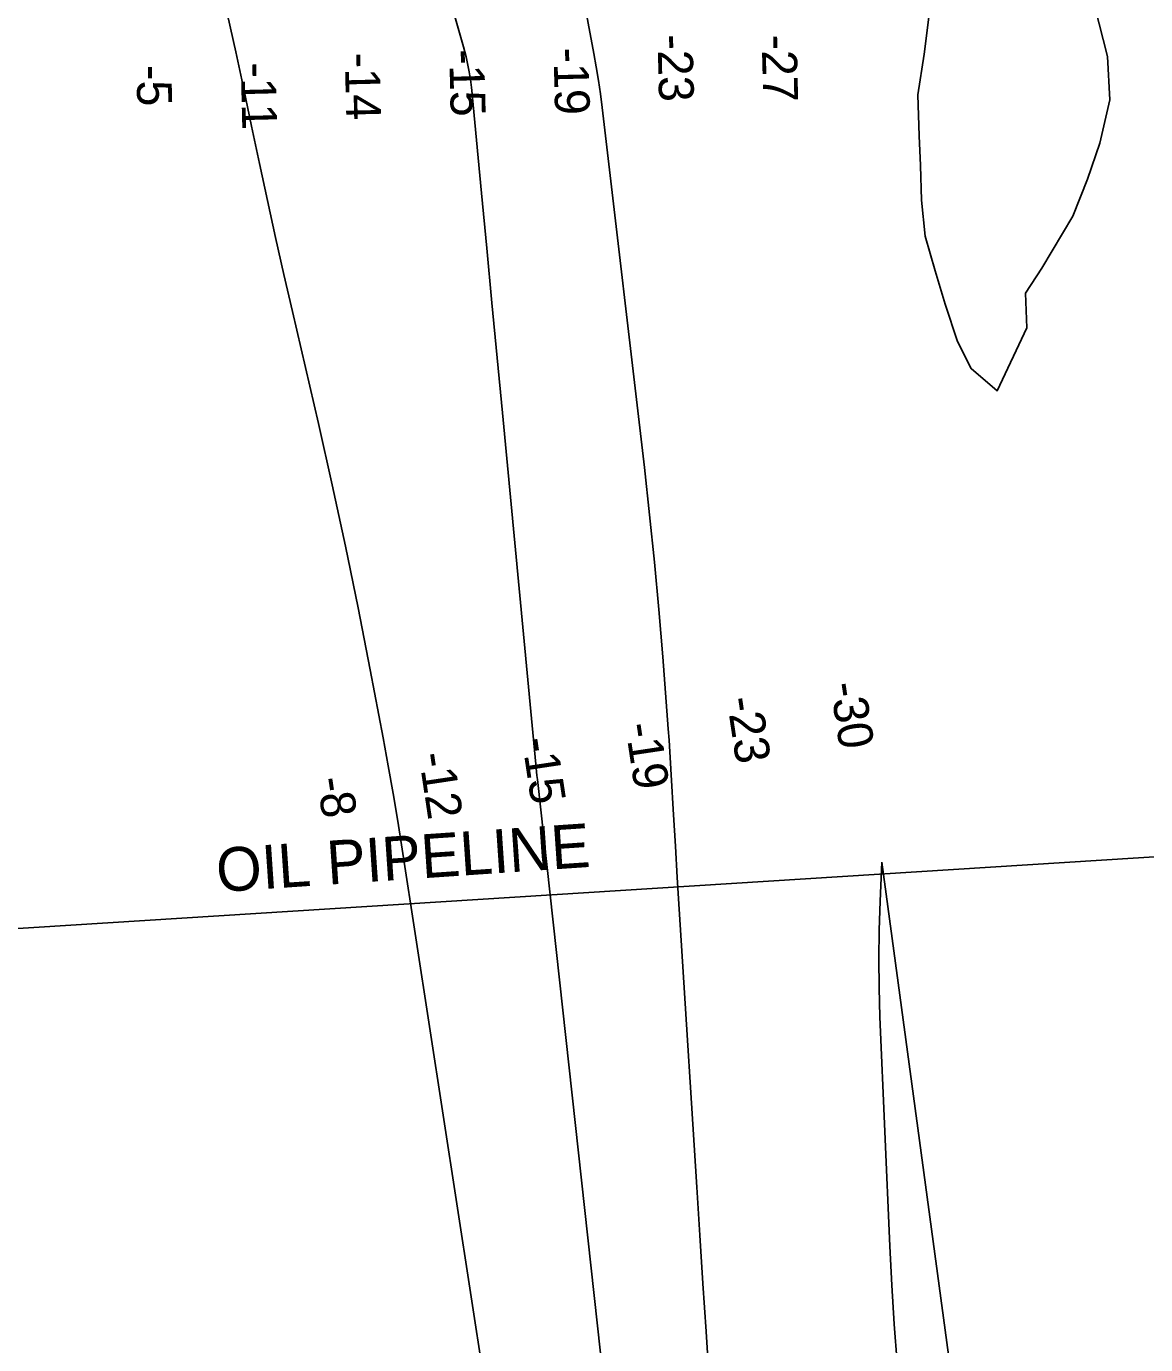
# Model space of a CAD drawing. Extents: x 3937982 to 3958556, y 219448 to 241894.
# Drawn here: x 3948252 to 3949325, y 230784 to 232047 of the extents above; entities that cross this region are included whole.
import ezdxf

# ---------------------------------------------------------------- set-up
doc = ezdxf.new("R2010")
doc.units = 0
for name, color, linetype in [('V-RIVR-EDGE', 7, 'Continuous'), ('V-RIVR-RANG', 7, 'Continuous'), ('V-TOPO-DPTH', 7, 'Continuous'), ('V-TOPO-MINR', 7, 'Continuous'), ('V-UTIL-IDEN', 7, 'Continuous'), ('V-UTIL-LINE', 7, 'Continuous')]:
    doc.layers.add(name, color=color, linetype=linetype)

msp = doc.modelspace()

# ---------------------------------------------------------------- linework, layer by layer
at = {"layer": 'V-RIVR-EDGE'}
msp.add_lwpolyline([(3949117.382, 232058.689), (3949112.633, 232020.698), (3949106.697, 231981.52), (3949107.884, 231942.342), (3949109.071, 231913.849), (3949110.258, 231880.607), (3949113.82, 231846.178), (3949123.318, 231812.936), (3949132.815, 231780.882), (3949144.687, 231745.265), (3949157.747, 231719.146), (3949182.678, 231697.777), (3949211.171, 231758.324), (3949209.984, 231791.566), (3949225.418, 231815.311), (3949255.098, 231865.174), (3949269.345, 231900.79), (3949281.217, 231935.219), (3949290.715, 231976.772), (3949288.34, 232018.324), (3949276.468, 232065.813)], dxfattribs=at)
at = {"layer": 'V-TOPO-DPTH'}
msp.add_line((3949335.18, 229299.97), (3949072.233, 231246.187), dxfattribs=at)
for points in [[(3948785.035, 232079.587), (3948796.105, 232021.135), (3948798.397, 232008.293), (3948800.507, 231995.422), (3948802.345, 231982.511), (3948804.001, 231969.571), (3948844.502, 231624.247), (3948849.537, 231578.945), (3948854.206, 231533.607), (3948858.326, 231488.216), (3948862.079, 231442.789), (3948867.355, 231373.85), (3948868.163, 231362.864), (3948868.927, 231351.876), (3948869.627, 231340.883), (3948870.284, 231329.887), (3948872.46, 231291.549), (3948874.202, 231261.383), (3948875.983, 231231.22), (3948877.823, 231201.061), (3948879.702, 231170.904), (3948894.659, 230934.576), (3948897.611, 230888.384), (3948900.601, 230842.195), (3948903.648, 230796.009), (3948906.732, 230749.826)], [(3948691.036, 230748.645), (3948612.317, 231258.504), (3948608.057, 231285.199), (3948603.617, 231311.864), (3948598.907, 231338.482), (3948594.018, 231365.07), (3948581.645, 231430.497), (3948570.072, 231489.699), (3948558.016, 231548.799), (3948545.235, 231607.746), (3948531.972, 231666.592), (3948507.119, 231773.786), (3948498.997, 231809.264), (3948491.005, 231844.771), (3948483.21, 231880.322), (3948475.545, 231915.902), (3948467.957, 231951.499), (3948460.341, 231987.089), (3948452.681, 232022.671), (3948444.992, 232058.246)], [(3948868.927, 231351.876), (3948869.627, 231340.883), (3948870.284, 231329.887), (3948872.46, 231291.549), (3948874.202, 231261.383), (3948875.983, 231231.22), (3948877.823, 231201.061), (3948879.702, 231170.904), (3948894.659, 230934.576), (3948897.611, 230888.384), (3948900.601, 230842.195), (3948903.648, 230796.009), (3948906.732, 230749.826)], [(3949086.893, 230765.99), (3949084.037, 230803.261), (3949081.756, 230840.571), (3949079.857, 230877.907), (3949070.364, 231097.917), (3949069.54, 231125.567), (3949069.208, 231153.217), (3949069.613, 231180.865), (3949070.509, 231208.513), (3949072.233, 231246.187)], [(3949072.233, 231246.187), (3949070.509, 231208.513), (3949069.613, 231180.865), (3949069.208, 231153.217), (3949069.54, 231125.567), (3949070.364, 231097.917), (3949079.857, 230877.907), (3949081.756, 230840.571), (3949084.037, 230803.261), (3949086.893, 230765.99)]]:
    msp.add_lwpolyline(points, dxfattribs=at)
at = {"layer": 'V-TOPO-MINR'}
for points in [[(3948484.624, 232682.01), (3948671.112, 232027.592), (3948672.419, 232022.851), (3948673.596, 232018.076), (3948674.683, 232013.282), (3948675.635, 232008.46), (3948676.498, 232003.619), (3948677.77, 231995.854), (3948678.03, 231994.162), (3948678.469, 231990.767), (3948678.649, 231989.065), (3948688.34, 231887.286), (3948693.347, 231834.692), (3948698.354, 231782.098), (3948703.361, 231729.504), (3948708.367, 231676.909), (3948740.443, 231339.883), (3948740.798, 231336.242), (3948741.163, 231332.603), (3948741.543, 231328.965), (3948741.935, 231325.328), (3948817.338, 230638.655)], [(3948785.035, 232079.587), (3948796.105, 232021.135), (3948798.397, 232008.293), (3948800.507, 231995.422), (3948802.345, 231982.511), (3948804.001, 231969.571), (3948844.502, 231624.247), (3948849.537, 231578.945), (3948854.206, 231533.607), (3948858.326, 231488.216), (3948862.079, 231442.789), (3948867.355, 231373.85), (3948868.163, 231362.864), (3948868.927, 231351.876), (3948869.627, 231340.883), (3948870.284, 231329.887), (3948872.46, 231291.549), (3948874.202, 231261.383), (3948875.983, 231231.22), (3948877.823, 231201.061), (3948879.702, 231170.904), (3948894.659, 230934.576), (3948897.611, 230888.384), (3948900.601, 230842.195), (3948903.648, 230796.009), (3948906.732, 230749.826)], [(3948444.992, 232058.246), (3948452.681, 232022.671), (3948460.341, 231987.089), (3948467.957, 231951.499), (3948475.545, 231915.902), (3948483.21, 231880.322), (3948491.005, 231844.771), (3948498.997, 231809.264), (3948507.119, 231773.786), (3948531.972, 231666.592), (3948545.235, 231607.746), (3948558.016, 231548.799), (3948570.072, 231489.699), (3948581.645, 231430.497), (3948594.018, 231365.07), (3948598.907, 231338.482), (3948603.617, 231311.864), (3948608.057, 231285.199), (3948612.317, 231258.504), (3948691.036, 230748.645)], [(3949072.233, 231246.187), (3949070.509, 231208.513), (3949069.613, 231180.865), (3949069.208, 231153.217), (3949069.54, 231125.567), (3949070.364, 231097.917), (3949079.857, 230877.907), (3949081.756, 230840.571), (3949084.037, 230803.261), (3949086.893, 230765.99)]]:
    msp.add_lwpolyline(points, dxfattribs=at)
at = {"layer": 'V-UTIL-LINE'}
msp.add_line((3947679.344, 231146.765), (3949584.13, 231267.067), dxfattribs=at)

# ---------------------------------------------------------------- texts
at = {"layer": 'V-RIVR-RANG'}
for s, rotation, p in [('-23', 271.409889, (3948857.052, 232039.223)), ('-19', 271.409889, (3948757.332, 232026.609)), ('-27', 271.409889, (3948956.886, 232039.055)), ('-14', 271.409889, (3948557.193, 232021.68)), ('-15', 271.409889, (3948657.34, 232025.07)), ('-5', 271.409889, (3948357.419, 232010.031)), ('-11', 271.409889, (3948457.492, 232012.364)), ('-30', 278.563222, (3949022.387, 231416.878)), ('-23', 278.563222, (3948923.267, 231402.872)), ('-19', 278.563222, (3948825.896, 231377.925)), ('-15', 278.563222, (3948726.876, 231363.934)), ('-12', 278.563222, (3948627.914, 231349.551)), ('-8', 278.563222, (3948530.327, 231326.039))]:
    msp.add_text(s, height=33.5, rotation=rotation, dxfattribs=at).set_placement(p)
at = {"layer": 'V-UTIL-IDEN'}
msp.add_text('OIL PIPELINE', height=41.99992, rotation=3.886609, dxfattribs=at).set_placement((3948435.412, 231217.218))

doc.saveas('drawing.dxf')
